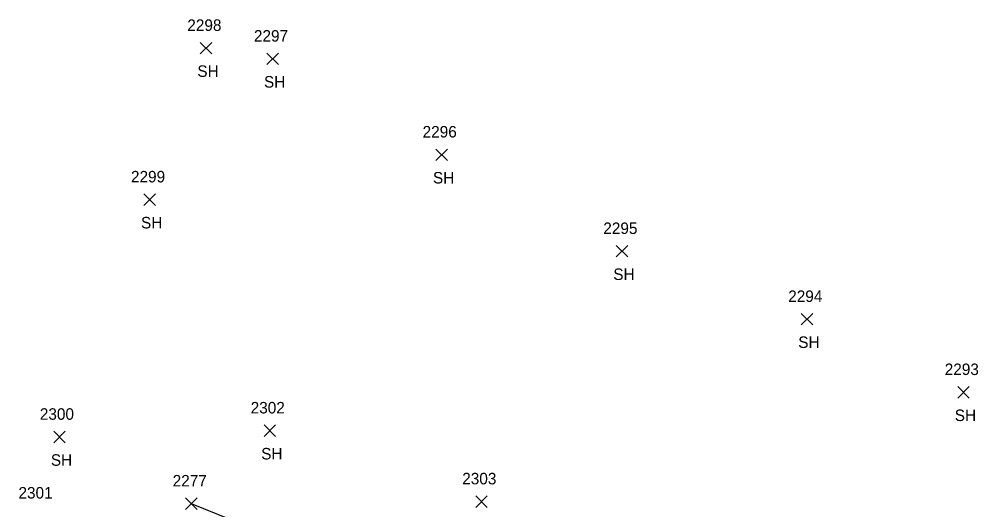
# Model space of a CAD drawing. Extents: x 1885914 to 1887218, y 756253 to 760620.
# Drawn here: x 1886478.4 to 1886645.8, y 760358 to 760443.3 of the extents above; entities that cross this region are included whole.
import ezdxf

# ---------------------------------------------------------------- set-up
doc = ezdxf.new("R2010")
doc.units = 0
for name, color, linetype in [('L_A', 7, 'Continuous'), ('L_I', 7, 'Continuous'), ('L_TIC', 7, 'Continuous'), ('LAWA', 7, 'Continuous')]:
    doc.layers.add(name, color=color, linetype=linetype)

msp = doc.modelspace()

# ---------------------------------------------------------------- linework, layer by layer
at = {"layer": 'L_TIC'}
for points in [[(1886509.89, 760437.23), (1886511.89, 760439.23)], [(1886511.89, 760437.23), (1886509.89, 760439.23)], [(1886521.49, 760435.37), (1886523.49, 760437.37)], [(1886523.49, 760435.37), (1886521.49, 760437.37)], [(1886550.91, 760418.69), (1886552.91, 760420.69)], [(1886552.91, 760418.69), (1886550.91, 760420.69)], [(1886500.08, 760410.88), (1886502.08, 760412.88)], [(1886502.08, 760410.88), (1886500.08, 760412.88)], [(1886582.31, 760401.91), (1886584.31, 760403.91)], [(1886584.31, 760401.91), (1886582.31, 760403.91)], [(1886614.52, 760390.09), (1886616.52, 760392.09)], [(1886616.52, 760390.09), (1886614.52, 760392.09)], [(1886641.77, 760377.38), (1886643.77, 760379.38)], [(1886643.77, 760377.38), (1886641.77, 760379.38)], [(1886484.38, 760369.6), (1886486.38, 760371.6)], [(1886486.38, 760369.6), (1886484.38, 760371.6)], [(1886521, 760370.7), (1886523, 760372.7)], [(1886523, 760370.7), (1886521, 760372.7)], [(1886507.34, 760358), (1886509.34, 760360)], [(1886509.34, 760358), (1886507.34, 760360)], [(1886557.84, 760358.37), (1886559.84, 760360.37)], [(1886559.84, 760358.37), (1886557.84, 760360.37)]]:
    msp.add_lwpolyline(points, dxfattribs=at)
at = {"layer": 'LAWA'}
msp.add_lwpolyline([(1886557.49, 760303.87), (1886591.46, 760287.38), (1886586.6, 760261.32), (1886572.4, 760231.51), (1886560.84, 760204.17), (1886553.53, 760184.95), (1886554.61, 760165.79), (1886555.43, 760150.16), (1886559.73, 760135.93), (1886571.71, 760133.88), (1886584.52, 760154.18), (1886595.31, 760177.7), (1886612.55, 760208.5), (1886627.73, 760237.63), (1886641.55, 760264.82), (1886659.69, 760306.49), (1886641.28, 760308.88), (1886618.53, 760315.27), (1886578.46, 760329), (1886533.46, 760348.84), (1886508.34, 760359)], dxfattribs=at)

# ---------------------------------------------------------------- texts
at = {"layer": 'L_A'}
for p in [(1886509.38, 760433.23), (1886520.98, 760431.37), (1886550.4, 760414.69), (1886499.57, 760406.88), (1886581.8, 760397.91), (1886614.01, 760386.09), (1886641.26, 760373.38), (1886520.49, 760366.7), (1886483.87, 760365.6)]:
    msp.add_text('SH', height=2, dxfattribs=at).set_placement(p)
at = {"layer": 'L_I'}
for s, p in [('2298', (1886507.63, 760441.23)), ('2297', (1886519.23, 760439.37)), ('2296', (1886548.6, 760422.69)), ('2299', (1886497.82, 760414.88)), ('2295', (1886580.06, 760405.91)), ('2294', (1886612.26, 760394.09)), ('2293', (1886639.51, 760381.38)), ('2302', (1886518.66, 760374.7)), ('2300', (1886481.95, 760373.6)), ('2277', (1886505.08, 760362)), ('2303', (1886555.5, 760362.37)), ('2301', (1886478.23, 760359.9))]:
    msp.add_text(s, height=2, dxfattribs=at).set_placement(p)

doc.saveas('drawing.dxf')
